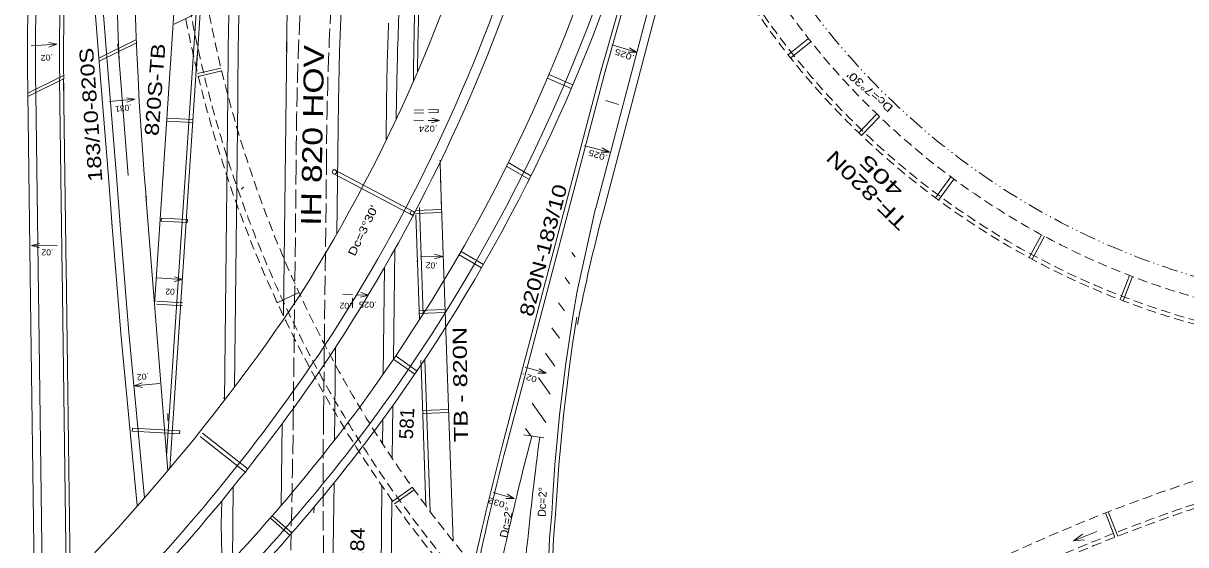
# Model space of a CAD drawing. Extents: x 2354993 to 2372084, y 6966390 to 6990057.
# Drawn here: x 2364225 to 2365387, y 6978118 to 6978638 of the extents above; entities that cross this region are included whole.
import ezdxf

# ---------------------------------------------------------------- set-up
doc = ezdxf.new("R2010")
doc.units = 0
doc.header["$LTSCALE"] = 3.2
for name, pattern in [('DASH_DOUBLE_DOT', [9.2, 5, -1.2, 0.3, -1.2, 0.3, -1.2]), ('LONG_DASHED', [7.5, 6, -1.5]), ('MEDIUM_DASHED', [4.5, 3, -1.5])]:
    doc.linetypes.add(name, pattern=pattern)
for name, color, linetype, lineweight in [('11', 7, 'Continuous', 13), ('12', 7, 'Continuous', 13), ('13', 7, 'Continuous', 13), ('14', 7, 'Continuous', 13), ('17', 7, 'Continuous', 13), ('19', 7, 'Continuous', 13), ('25', 7, 'Continuous', 13), ('28', 7, 'Continuous', 13), ('30', 7, 'Continuous', 13), ('4', 7, 'Continuous', 13), ('5', 7, 'Continuous', 13), ('59', 7, 'Continuous', 13), ('6', 7, 'Continuous', 13), ('60', 7, 'DASH_DOUBLE_DOT', 13), ('61', 7, 'Continuous', 13), ('7', 7, 'Continuous', 13), ('9', 7, 'Continuous', 13)]:
    doc.layers.add(name, color=color, linetype=linetype, lineweight=lineweight)

msp = doc.modelspace()

# ---------------------------------------------------------------- linework, layer by layer
at = {"layer": '12'}
for p, q in [((2364300.561, 6978603.539), (2364337.984, 6978622.028)), ((2364229.456, 6978568.406), (2364265.276, 6978586.105)), ((2364422.53, 6978593.603), (2364399.184, 6978588.037)), ((2364423.235, 6978590.687), (2364399.889, 6978585.121)), ((2364750.355, 6978587.086), (2364774.249, 6978576.836)), ((2364748.778, 6978583.41), (2364772.671, 6978573.16)), ((2364229.452, 6978568.704), (2364232.173, 6978361.901)), ((2364394.329, 6978539.14), (2364368.369, 6978540.599)), ((2364394.528, 6978542.133), (2364368.568, 6978543.592)), ((2364535.309, 6978492.345), (2364616.657, 6978449.5)), ((2364708.082, 6978495.399), (2364730.36, 6978482.609)), ((2364710.073, 6978498.868), (2364732.351, 6978486.078)), ((2364314.268, 6978430.633), (2364309.968, 6978484.875)), ((2364534.549, 6978488.225), (2364614.793, 6978445.961)), ((2364445.177, 6978474.693), (2364443.065, 6978472.563)), ((2364642.983, 6978452.418), (2364616.998, 6978451.499)), ((2364643.114, 6978449.419), (2364617.13, 6978448.502)), ((2364388.851, 6978439.288), (2364362.893, 6978440.747)), ((2364389.019, 6978442.283), (2364388.851, 6978439.288)), ((2364662.488, 6978410.551), (2364684.865, 6978397.416)), ((2364618.872, 6978398.533), (2364618.766, 6978401.531)), ((2364660.463, 6978407.102), (2364682.84, 6978393.967)), ((2364384.189, 6978356.304), (2364358.231, 6978357.762)), ((2364384.356, 6978359.299), (2364358.398, 6978360.757)), ((2364646.517, 6978352.48), (2364620.532, 6978351.561)), ((2364646.641, 6978349.481), (2364620.657, 6978348.564)), ((2364597.72, 6978305.879), (2364618.45, 6978291.12)), ((2364595.4, 6978302.62), (2364616.13, 6978287.862)), ((2364622.406, 6978298.595), (2364622.3, 6978301.593)), ((2364650.051, 6978252.542), (2364624.066, 6978251.623)), ((2364650.168, 6978249.543), (2364624.184, 6978248.626)), ((2364334.007, 6978233.889), (2364333.84, 6978230.894)), ((2364381.236, 6978228.23), (2364333.84, 6978230.894)), ((2364381.403, 6978231.225), (2364334.007, 6978233.889)), ((2364381.403, 6978231.225), (2364381.236, 6978228.23)), ((2364401.638, 6978225.773), (2364447.213, 6978189.9)), ((2364404.112, 6978228.916), (2364449.687, 6978193.043)), ((2364625.834, 6978201.655), (2364625.94, 6978198.657)), ((2365316.038, 6978125.129), (2365306.599, 6978149.356)), ((2365318.832, 6978126.22), (2365309.393, 6978150.447))]:
    msp.add_line(p, q, dxfattribs=at)
msp.add_lwpolyline([(2364389.019, 6978442.283), (2364363.061, 6978443.742), (2364362.893, 6978440.747)], dxfattribs=at)
for centre, radius in [((2364535.877, 6978489.877), 2.162), ((2364613.685, 6978448.959), 1.938)]:
    msp.add_circle(centre, radius, dxfattribs=at)
at = {"layer": '14'}
for p, q in [((2365297.86, 6978130.914), (2365274.708, 6978121.481)), ((2365274.708, 6978121.481), (2365283.433, 6978128.312)), ((2365274.708, 6978121.481), (2365285.722, 6978122.692))]:
    msp.add_line(p, q, dxfattribs=at)
at = {"layer": '17', "linetype": 'MEDIUM_DASHED'}
for p, q in [((2364639.449, 6978552.356), (2364613.464, 6978551.437)), ((2364639.587, 6978549.357), (2364613.603, 6978548.44)), ((2364639.607, 6978549.358), (2364639.501, 6978552.35))]:
    msp.add_line(p, q, dxfattribs=at)
at = {"layer": '19'}
for p, q in [((2364258.429, 6978617.301), (2364250.566, 6978614.606)), ((2364837.919, 6978609.382), (2364829.608, 6978609.51)), ((2364336.356, 6978562.411), (2364328.572, 6978559.496)), ((2364810.814, 6978509.763), (2364802.508, 6978509.456)), ((2364233.097, 6978416.421), (2364241.133, 6978418.549)), ((2364643.882, 6978405.298), (2364635.855, 6978403.138)), ((2364383.93, 6978382.36), (2364375.805, 6978380.608)), ((2364747.593, 6978288.913), (2364739.28, 6978288.905)), ((2364335.857, 6978276.331), (2364343.614, 6978279.319)), ((2364715.597, 6978163.89), (2364707.284, 6978163.882))]:
    msp.add_line(p, q, dxfattribs=at)
at = {"layer": '19', "linetype": 'MEDIUM_DASHED'}
for p, q in [((2364641.081, 6978541.158), (2364633.062, 6978538.971)), ((2364553.948, 6978363.903), (2364553.909, 6978353.058)), ((2364570.118, 6978366.76), (2364562.037, 6978364.816))]:
    msp.add_line(p, q, dxfattribs=at)
at = {"layer": '19'}
for points in [[(2364232.682, 6978615.945), (2364258.429, 6978617.301), (2364250.332, 6978619.153)], [(2364813.234, 6978616.83), (2364837.919, 6978609.382), (2364830.928, 6978613.868)], [(2364310.657, 6978560.33), (2364336.356, 6978562.411), (2364328.21, 6978564.034)], [(2364785.774, 6978515.909), (2364810.814, 6978509.763), (2364803.598, 6978513.878)], [(2364258.876, 6978415.937), (2364233.097, 6978416.421), (2364241.041, 6978413.996)], [(2364621.96, 6978405.618), (2364643.882, 6978405.298), (2364635.927, 6978407.69)], [(2364358.202, 6978384.04), (2364383.93, 6978382.36), (2364376.107, 6978385.151)], [(2364726.501, 6978294.896), (2364747.593, 6978288.913), (2364740.528, 6978293.283)], [(2364361.536, 6978278.65), (2364335.857, 6978276.331), (2364344.017, 6978274.783)], [(2364694.505, 6978169.873), (2364715.597, 6978163.89), (2364708.532, 6978168.26)]]:
    msp.add_lwpolyline(points, dxfattribs=at)
at = {"layer": '19', "linetype": 'MEDIUM_DASHED'}
for points in [[(2364615.297, 6978541.45), (2364641.081, 6978541.158), (2364633.118, 6978543.524)], [(2364544.358, 6978367.832), (2364570.118, 6978366.76), (2364562.232, 6978369.365)]]:
    msp.add_lwpolyline(points, dxfattribs=at)
at = {"layer": '25'}
for p, q in [((2364368.17, 6978206.229), (2364399.023, 6978669.972)), ((2364488.071, 6978609.665), (2364488.557, 6978650.842)), ((2364484.961, 6978346.199), (2364488.209, 6978621.342)), ((2364307.528, 6978616.887), (2364317.943, 6978485.507)), ((2364319.49, 6978617.835), (2364329.905, 6978486.455)), ((2364587.534, 6978521.179), (2364588.019, 6978562.233)), ((2364538.433, 6978428.325), (2364539.995, 6978560.576)), ((2364321.764, 6978437.311), (2364317.943, 6978485.507)), ((2364330.314, 6978329.457), (2364321.473, 6978440.986)), ((2364584.781, 6978288.034), (2364586.041, 6978394.75)), ((2364330.314, 6978329.457), (2364346.159, 6978164.504)), ((2364482.725, 6978156.923), (2364483.686, 6978238.319)), ((2364583.963, 6978218.733), (2364584.244, 6978242.506)), ((2364535.5, 6978179.675), (2364533.978, 6978050.938)), ((2364581.463, 6978007.018), (2364583.464, 6978176.442))]:
    msp.add_line(p, q, dxfattribs=at)
msp.add_lwpolyline([(2364537.098, 6978314.898), (2364536.33, 6978249.932), (2364536, 6978222.017)], dxfattribs=at)
for centre, radius, start, end in [((2367605.673, 6978746.13), 3288.045, 157.44674, 182.51497), ((2367364.087, 6978527.237), 2824.289, 157.96111, 179.32363), ((2367749.981, 6978912.12), 3455.09, 180.35624, 184.90183), ((2367364.086, 6978527.232), 2776.289, 177.7069, 179.27765)]:
    msp.add_arc(centre, radius, start, end, dxfattribs=at)
at = {"layer": '25', "linetype": 'LONG_DASHED'}
msp.add_arc((2367534.289, 6978489.569), 3006.329, 158.51286, 179.87539, dxfattribs=at)
at = {"layer": '28'}
msp.add_line((2364807.177, 6978561.252), (2364819.762, 6978557.297), dxfattribs=at)
at = {"layer": '30'}
msp.add_line((2364369.278, 6978241.689), (2364369.359, 6978248.572), dxfattribs=at)
at = {"layer": '4'}
for p, q in [((2364299.557, 6978616.203), (2364309.968, 6978484.875)), ((2364597.787, 6978542.58), (2364598.018, 6978562.115)), ((2364594.957, 6978302.811), (2364596.255, 6978412.759)), ((2364593.789, 6978203.885), (2364594.411, 6978256.582)), ((2364591.974, 6978050.253), (2364593.298, 6978162.457))]:
    msp.add_line(p, q, dxfattribs=at)
for centre, radius, start, end in [((2367605.673, 6978746.13), 3270.045, 157.44674, 184.53246), ((2367125.989, 6978606.822), 2860.789, 174.29027, 180.48169), ((2367749.981, 6978912.12), 3463.09, 180.35624, 184.90183), ((2367364.086, 6978527.232), 2766.289, 177.41838, 179.27765)]:
    msp.add_arc(centre, radius, start, end, dxfattribs=at)
at = {"layer": '5'}
for p, q in [((2364797.288, 6978453.72), (2364856.416, 6978677.989)), ((2364829.342, 6978685.127), (2364801.736, 6978589.013)), ((2364833.209, 6978684.108), (2364805.681, 6978587.971)), ((2364356.183, 6978357.451), (2364377.072, 6978671.432)), ((2364397.931, 6978593.3), (2364403.014, 6978669.706)), ((2364805.021, 6978451.673), (2364864.153, 6978675.957)), ((2364371.359, 6978193.923), (2364398.813, 6978606.559)), ((2364703.961, 6978217.401), (2364803.248, 6978593.999)), ((2364707.829, 6978216.381), (2364807.115, 6978592.979)), ((2364263.839, 6978387.483), (2364261.27, 6978582.702)), ((2364267.797, 6978390.761), (2364265.27, 6978582.755)), ((2364240.093, 6978368.193), (2364237.452, 6978568.809)), ((2364425.903, 6978261.761), (2364429.49, 6978566.1)), ((2364439.162, 6978533.446), (2364439.501, 6978561.758)), ((2364436.064, 6978275.086), (2364439.162, 6978533.446)), ((2364347.958, 6978461.222), (2364345.856, 6978487.735)), ((2364369.336, 6978191.519), (2364347.579, 6978465.988)), ((2364620.869, 6978342.06), (2364617.157, 6978447.031)), ((2364624.662, 6978348.013), (2364620.895, 6978454.534)), ((2364654.697, 6978121.177), (2364642.881, 6978455.312)), ((2364322.328, 6978328.965), (2364313.602, 6978439.055)), ((2364773.207, 6978409.446), (2364776.385, 6978405.016)), ((2364267.888, 6978079.876), (2364263.771, 6978392.69)), ((2364271.836, 6978083.919), (2364267.734, 6978395.661)), ((2364766.591, 6978384.353), (2364770.987, 6978378.224)), ((2364236.303, 6978048.324), (2364232.175, 6978361.911)), ((2364759.976, 6978359.259), (2364765.799, 6978351.14)), ((2364774.327, 6978320.294), (2364778.131, 6978344.982)), ((2364322.351, 6978328.693), (2364338.849, 6978156.952)), ((2364753.36, 6978334.166), (2364760.827, 6978323.754)), ((2364770.905, 6978295.883), (2364774.335, 6978320.348)), ((2364746.745, 6978309.072), (2364756.078, 6978296.057)), ((2364627.435, 6978156.378), (2364622.46, 6978297.071)), ((2364631.637, 6978150.774), (2364626.262, 6978302.759)), ((2364767.753, 6978271.136), (2364770.911, 6978295.933)), ((2364724.995, 6978288.444), (2364724.259, 6978288.151)), ((2364740.129, 6978283.979), (2364751.558, 6978268.041)), ((2364764.959, 6978246.559), (2364767.759, 6978271.19)), ((2364733.513, 6978258.885), (2364747.275, 6978239.696)), ((2364762.413, 6978221.397), (2364764.964, 6978246.609)), ((2364745.09, 6978224.447), (2364725.284, 6978227.231)), ((2364726.898, 6978233.792), (2364732.311, 6978226.243)), ((2364729.102, 6978210.773), (2364733.15, 6978226.125)), ((2364760.301, 6978197.005), (2364762.419, 6978221.455)), ((2364758.47, 6978172.248), (2364760.305, 6978197.055)), ((2364433.986, 6978101.712), (2364434.867, 6978175.192)), ((2364757.039, 6978148.259), (2364758.473, 6978172.305)), ((2364754.859, 6978123.602), (2364757.03, 6978148.145)), ((2364423.845, 6978091.472), (2364422.744, 6978138.5)), ((2364753.829, 6978098.812), (2364754.871, 6978123.787))]:
    msp.add_line(p, q, dxfattribs=at)
at = {"layer": '5', "linetype": 'LONG_DASHED'}
for p, q in [((2364497.721, 6978496.465), (2364494.781, 6978247.382)), ((2364525.028, 6978247.025), (2364527.968, 6978496.107))]:
    msp.add_line(p, q, dxfattribs=at)
at = {"layer": '5'}
msp.add_lwpolyline([(2364748.237, 6978049.03), (2364748.453, 6978074.017), (2364749.833, 6978098.979), (2364750.875, 6978123.954), (2364753.046, 6978148.498), (2364754.481, 6978172.543), (2364756.316, 6978197.35), (2364758.434, 6978221.8), (2364760.985, 6978247.011), (2364763.785, 6978271.641), (2364766.943, 6978296.439), (2364770.374, 6978320.903), (2364774.178, 6978345.591), (2364778.407, 6978370.695), (2364796.946, 6978453.796)], dxfattribs=at)
for centre, radius, start, end in [((2367632.915, 6978563.806), 3014, 163.73512, 179.50178), ((2367125.99, 6978606.822), 2888.789, 171.16905, 180.75397), ((2367125.99, 6978606.822), 2864.789, 173.35232, 180.48169), ((2367125.99, 6978606.822), 2896.789, 173.81247, 180.82559), ((2363217.727, 6979240.251), 1666, 323.74727, 347.27016), ((2367632.915, 6978563.806), 3018, 174.25411, 179.68592), ((2363217.727, 6979240.251), 1684, 323.49687, 346.83945), ((2363127.192, 6979233.99), 1625.022, 327.75883, 346.05765), ((2363217.727, 6979240.251), 1692, 323.39108, 343.06808), ((2363127.192, 6979233.99), 1673.022, 326.75894, 342.55536), ((2363127.192, 6979233.99), 1683.022, 326.53499, 342.55536), ((2367395.528, 6978571.704), 2966.044, 178.45373, 180.10824), ((2367395.528, 6978571.704), 2956.044, 178.45373, 180.19276), ((2367125.99, 6978606.822), 2860.789, 180.56908, 180.75397), ((2367633.012, 6978561.052), 2992, 181.13725, 182.02529), ((2367632.915, 6978563.806), 2992, 181.31084, 182.02528), ((2366632.436, 6977969.881), 1889.859, 165.23027, 168.77793), ((2362823.255, 6979494.499), 2021.91, 312.68984, 326.1095), ((2363014.544, 6979325.529), 1817.476, 315.51277, 326.29202), ((2363008.703, 6979329.968), 1834.853, 315.90902, 326.07506), ((2363083.622, 6979356.349), 1842.854, 314.93085, 323.30202), ((2363244.672, 6976597.082), 1645.014, 38.12295, 103.3303), ((2363069.263, 6979367.953), 1879.359, 315.5386, 323.05986), ((2363062.003, 6979373.816), 1896.709, 315.80261, 322.95759), ((2368298.716, 6977752.87), 3588.778, 172.43843, 175.94649), ((2363244.672, 6976597.082), 1623.014, 38.12295, 103.3303), ((2363244.672, 6976597.082), 1619.014, 38.12295, 103.3303), ((2368172.363, 6977322.346), 3582.03, 165.52996, 167.99765), ((2368154.706, 6977326.865), 3559.803, 165.52972, 168.05788), ((2368799.967, 6977188.312), 4197.305, 165.90092, 168.75683)]:
    msp.add_arc(centre, radius, start, end, dxfattribs=at)
at = {"layer": '5', "linetype": 'MEDIUM_DASHED'}
for centre, radius, start, end in [((2365591.415, 6978874.774), 1226.227, 157.96139, 222.27477), ((2365591.415, 6978874.774), 1220.227, 157.96139, 222.48424), ((2365591.415, 6978874.774), 1202.227, 157.96139, 223.28034), ((2365602.828, 6979091.775), 755.944, 184.10697, 276.23324), ((2365602.828, 6979091.775), 777.944, 184.10654, 276.23324), ((2365602.828, 6979091.775), 781.944, 185.55228, 276.23324), ((2365952.337, 6976500.333), 1770.947, 100.46125, 118.99651), ((2365952.338, 6976500.332), 1748.947, 99.58224, 117.67913), ((2365952.338, 6976500.332), 1744.947, 99.58224, 117.42976)]:
    msp.add_arc(centre, radius, start, end, dxfattribs=at)
at = {"layer": '5', "linetype": 'LONG_DASHED'}
for centre, radius, start, end in [((2367702.294, 6978491.735), 3204.576, 168.65748, 179.91543), ((2355201.239, 6978357.07), 9294.189, 357.45391, 359.3238), ((2370414.262, 6978177.512), 5889.645, 179.32374, 181.73104)]:
    msp.add_arc(centre, radius, start, end, dxfattribs=at)
at = {"layer": '59'}
msp.add_line((2364515.415, 6978149.616), (2364515.511, 6978155.73), dxfattribs=at)
at = {"layer": '6'}
for p, q in [((2364375.629, 6978637.281), (2364401.715, 6978650.17)), ((2364300.816, 6978600.318), (2364338.11, 6978618.744)), ((2364229.5, 6978565.082), (2364265.27, 6978582.755)), ((2364244.21, 6978056.977), (2364240.055, 6978371.067)), ((2364344.497, 6978181.803), (2364346.147, 6978164.63))]:
    msp.add_line(p, q, dxfattribs=at)
at = {"layer": '60'}
msp.add_arc((2365602.828, 6979091.775), 735.944, 200.58365, 276.23324, dxfattribs=at)
at = {"layer": '61'}
for p, q in [((2365009.732, 6978623.066), (2364989.781, 6978607.299)), ((2365012.212, 6978619.928), (2364992.261, 6978604.161)), ((2365077.97, 6978547.739), (2365059.918, 6978529.028)), ((2365080.848, 6978544.962), (2365062.796, 6978526.251)), ((2365152.147, 6978484.856), (2365136.748, 6978463.917)), ((2365154.967, 6978482.783), (2365139.563, 6978461.837)), ((2365242.476, 6978427.238), (2365230.191, 6978404.332)), ((2365245.56, 6978425.584), (2365233.272, 6978402.671)), ((2365330.465, 6978386.602), (2365321.097, 6978362.348)), ((2365333.516, 6978385.431), (2365324.253, 6978361.137)), ((2364500.375, 6978369.6), (2364478.723, 6978359.245)), ((2364425.499, 6978264.579), (2364425.478, 6978263.601)), ((2364613.809, 6978175.035), (2364594.298, 6978161.06)), ((2364615.563, 6978172.601), (2364596.051, 6978158.625)), ((2364423.242, 6978161.309), (2364422.744, 6978138.5)), ((2364491.769, 6978126.838), (2364472.005, 6978144.049)), ((2364493.74, 6978129.1), (2364473.975, 6978146.311))]:
    msp.add_line(p, q, dxfattribs=at)
at = {"layer": '9'}
msp.add_arc((2360722.521, 6984327.136), 5729.573, 359.50797, 359.50797, dxfattribs=at)

# ---------------------------------------------------------------- texts
at = {"layer": '11'}
for s, rotation, width, p in [('.02', 178.117, 1.05, (2364639.064, 6978399.301)), ('.02', 163.117, 1.2, (2364741.386, 6978284.368)), ('.032', 163.117, 1.25, (2364709.39, 6978159.345))]:
    msp.add_text(s, height=6, rotation=rotation, dxfattribs=dict(at, width=width)).set_placement(p)
at = {"layer": '13'}
for s, height, rotation, width, p in [('183/10-820S', 14, 93.997, 1.25, (2364304.033, 6978480.531)), ('820S-TB', 14, 85.631, 1.25, (2364360.044, 6978525.517)), ('IH 820 HOV', 20, 88.969, 1.25, (2364522.394, 6978436.044)), ('TF-820N', 14, 135.829, 1.4, (2365110.183, 6978440.585)), ('405', 14, 135.42, 1.65, (2365105.722, 6978472.517)), ('820N-183/10', 14, 75.091, 1.25, (2364733.995, 6978344.476)), ('TB - 820N ', 14, 90.783, 1.35, (2364669.499, 6978220.06)), ('4,184', 14, 88.164, 1.15, (2364564.684, 6978080.867))]:
    msp.add_text(s, height=height, rotation=rotation, dxfattribs=dict(at, width=width)).set_placement(p)
msp.add_text('581', height=14, rotation=87.418, dxfattribs=at).set_placement((2364614.417, 6978222.755))
at = {"layer": '17'}
for s, rotation, width, p in [("Dc=7°30'", 139.372, 1.3, (2365095.099, 6978554.869)), ("Dc=3°30'", 64.213, 1.25, (2364556.265, 6978405.152))]:
    msp.add_text(s, height=7.999, rotation=rotation, dxfattribs=dict(at, width=width)).set_placement(p)
at = {"layer": '19'}
for s, height, rotation, width, p in [('.02', 6, 185.189, 1.1, (2364254.333, 6978607.529)), ('.025', 6, 159.703, 1.3, (2364836.434, 6978606.134)), ('.031', 6, 186.803, 1.05, (2364332.823, 6978557.432)), ('.024', 6, 181.377, 1.2, (2364638.893, 6978536.304)), ('.025', 6, 162.703, 1.25, (2364809.503, 6978506.442)), ('.02', 6, 181.098, 1.05, (2364254.894, 6978412.688)), ('.02', 6, 178.438, 1.05, (2364378.714, 6978373.137)), ('.02', 5.999, 178.287, 1.05, (2364552.967, 6978359.03)), ('.025', 6, 179.794, 1.15, (2364578.36, 6978360.372)), ('.02', 6, 187.333, 1.1, (2364350.193, 6978289.131))]:
    msp.add_text(s, height=height, rotation=rotation, dxfattribs=dict(at, width=width)).set_placement(p)
at = {"layer": '7'}
msp.add_text('Dc=2°', height=8, rotation=87.759, dxfattribs=at).set_placement((2364747.018, 6978145.42))
at = {"layer": '7', "width": 1.05}
msp.add_text('Dc=2°', height=8, rotation=78.787, dxfattribs=at).set_placement((2364708.829, 6978123.909))

doc.saveas('drawing.dxf')
